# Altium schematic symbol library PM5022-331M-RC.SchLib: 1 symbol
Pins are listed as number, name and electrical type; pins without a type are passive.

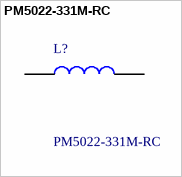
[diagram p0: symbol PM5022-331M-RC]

## PM5022-331M-RC
designator L?
Fixed Inductors 330uH 20% ,,; Manufacturer_Name: Bourns; Geometry.Height: 6.9mm
footprint PM5022331MRC
pins: 1, 2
